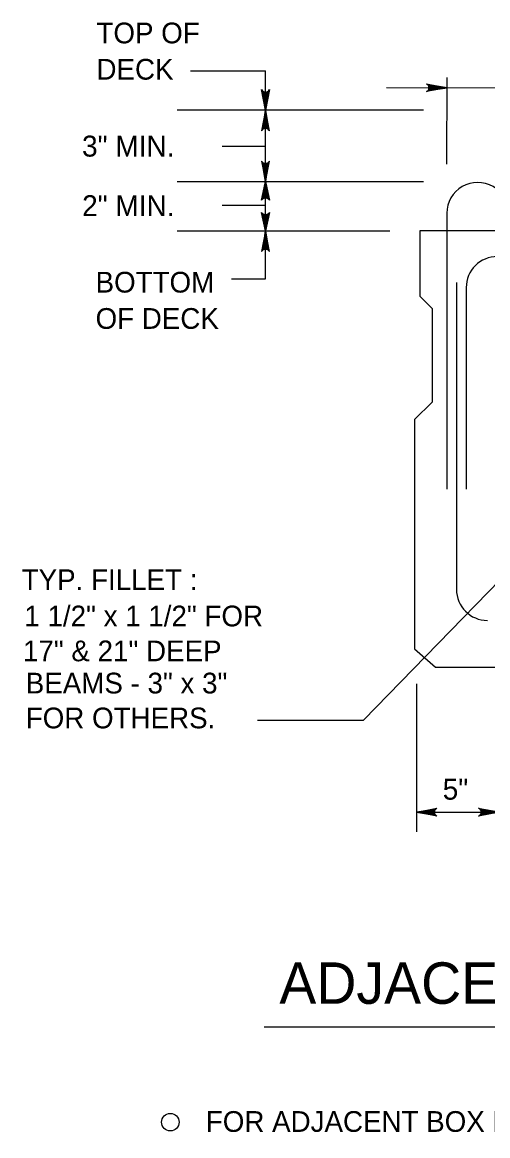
# Model space of a CAD drawing. Extents: x 639331 to 643089, y 299088 to 300975.
# Drawn here: x 640737.4 to 640804.7, y 299972.3 to 300133.4 of the extents above; entities that cross this region are included whole.
import ezdxf

# ---------------------------------------------------------------- set-up
doc = ezdxf.new("R2010")
doc.units = 0
doc.layers.add('1', color=7, linetype='Continuous')

msp = doc.modelspace()

# ---------------------------------------------------------------- linework, layer by layer
at = {"layer": '1'}
for p, q in [((640761.7, 300126.43), (640772.55, 300126.43)), ((640772.55, 300120.71), (640772.55, 300126.43)), ((640798.79, 300112.93), (640798.81, 300125.47)), ((640790.04, 300123.99), (640833.01, 300123.91)), ((640795.38, 300120.71), (640759.78, 300120.71)), ((640772.55, 300110.38), (640772.55, 300120.71)), ((640772.55, 300115.47), (640766.26, 300115.47)), ((640759.78, 300110.38), (640795.38, 300110.38)), ((640772.55, 300103.25), (640772.55, 300110.38)), ((640772.59, 300106.92), (640766.26, 300106.92)), ((640798.78, 300105.81), (640798.78, 300065.86)), ((640759.78, 300103.25), (640790.51, 300103.25)), ((640772.55, 300096.33), (640772.55, 300103.15)), ((640905.9, 300103.25), (640794.85, 300103.25)), ((640794.85, 300103.25), (640794.85, 300093.82)), ((640767.62, 300096.33), (640772.55, 300096.33)), ((640798.78, 300095.8), (640798.78, 300065.86)), ((640800.18, 300095.8), (640800.18, 300051.34)), ((640801.58, 300095.04), (640801.58, 300065.86)), ((640794.85, 300093.82), (640796.65, 300092.02)), ((640796.65, 300092.02), (640796.65, 300078.48)), ((640794.11, 300075.94), (640796.65, 300078.48)), ((640794.11, 300075.94), (640794.11, 300042.75)), ((640809.14, 300055.51), (640786.72, 300032.44)), ((640794.11, 300042.75), (640797.14, 300040.1)), ((640797.14, 300040.1), (640903.61, 300040.1)), ((640794.37, 300037.7), (640794.37, 300016.29)), ((640771.4, 300032.44), (640786.72, 300032.44)), ((640794.37, 300019.13), (640806.36, 300019.13)), ((640772.36, 299988.08), (640925.24, 299988.08))]:
    msp.add_line(p, q, dxfattribs=at)
for points in [[(640772.55, 300120.71), (640771.99, 300123.7), (640772.07, 300123.58), (640772.15, 300123.47), (640772.25, 300123.41), (640772.35, 300123.35), (640772.45, 300123.33), (640772.55, 300123.31), (640772.65, 300123.33), (640772.75, 300123.35), (640772.85, 300123.41), (640772.95, 300123.47), (640773.03, 300123.58), (640773.11, 300123.7), (640772.55, 300120.71), (640773.03, 300123.58), (640772.95, 300123.47), (640772.55, 300120.71), (640772.85, 300123.41), (640772.75, 300123.35), (640772.55, 300120.71), (640772.65, 300123.33), (640772.55, 300123.31), (640772.55, 300120.71), (640772.45, 300123.33), (640772.35, 300123.35), (640772.55, 300120.71), (640772.25, 300123.41), (640772.15, 300123.47), (640772.55, 300120.71), (640772.07, 300123.58)], [(640798.81, 300123.98), (640795.83, 300123.42), (640795.94, 300123.5), (640796.06, 300123.58), (640796.12, 300123.68), (640796.18, 300123.78), (640796.19, 300123.88), (640796.21, 300123.98), (640796.19, 300124.08), (640796.18, 300124.18), (640796.12, 300124.28), (640796.06, 300124.38), (640795.94, 300124.46), (640795.83, 300124.54), (640798.81, 300123.98), (640795.94, 300124.46), (640796.06, 300124.38), (640798.81, 300123.98), (640796.12, 300124.28), (640796.18, 300124.18), (640798.81, 300123.98), (640796.19, 300124.08), (640796.21, 300123.98), (640798.81, 300123.98), (640796.19, 300123.88), (640796.18, 300123.78), (640798.81, 300123.98), (640796.12, 300123.68), (640796.06, 300123.58), (640798.81, 300123.98), (640795.94, 300123.5)], [(640772.55, 300120.71), (640771.99, 300117.73), (640772.07, 300117.85), (640772.15, 300117.96), (640772.25, 300118.02), (640772.35, 300118.08), (640772.45, 300118.1), (640772.55, 300118.11), (640772.65, 300118.1), (640772.75, 300118.08), (640772.85, 300118.02), (640772.95, 300117.96), (640773.03, 300117.85), (640773.11, 300117.73), (640772.55, 300120.71), (640773.03, 300117.85), (640772.95, 300117.96), (640772.55, 300120.71), (640772.85, 300118.02), (640772.75, 300118.08), (640772.55, 300120.71), (640772.65, 300118.1), (640772.55, 300118.11), (640772.55, 300120.71), (640772.45, 300118.1), (640772.35, 300118.08), (640772.55, 300120.71), (640772.25, 300118.02), (640772.15, 300117.96), (640772.55, 300120.71), (640772.07, 300117.85)], [(640772.55, 300110.38), (640773.11, 300113.36), (640773.03, 300113.25), (640772.95, 300113.13), (640772.85, 300113.07), (640772.75, 300113.01), (640772.65, 300113), (640772.55, 300112.98), (640772.45, 300113), (640772.35, 300113.01), (640772.25, 300113.07), (640772.15, 300113.13), (640772.07, 300113.25), (640771.99, 300113.36), (640772.55, 300110.38), (640772.07, 300113.25), (640772.15, 300113.13), (640772.55, 300110.38), (640772.25, 300113.07), (640772.35, 300113.01), (640772.55, 300110.38), (640772.45, 300113), (640772.55, 300112.98), (640772.55, 300110.38), (640772.65, 300113), (640772.75, 300113.01), (640772.55, 300110.38), (640772.85, 300113.07), (640772.95, 300113.13), (640772.55, 300110.38), (640773.03, 300113.25)], [(640772.55, 300110.38), (640773.11, 300107.69), (640773.03, 300107.8), (640772.95, 300107.9), (640772.85, 300107.95), (640772.75, 300108.01), (640772.65, 300108.02), (640772.55, 300108.04), (640772.45, 300108.02), (640772.35, 300108.01), (640772.25, 300107.95), (640772.15, 300107.9), (640772.07, 300107.8), (640771.99, 300107.69), (640772.55, 300110.38), (640772.07, 300107.8), (640772.15, 300107.9), (640772.55, 300110.38), (640772.25, 300107.95), (640772.35, 300108.01), (640772.55, 300110.38), (640772.45, 300108.02), (640772.55, 300108.04), (640772.55, 300110.38), (640772.65, 300108.02), (640772.75, 300108.01), (640772.55, 300110.38), (640772.85, 300107.95), (640772.95, 300107.9), (640772.55, 300110.38), (640773.03, 300107.8)], [(640772.55, 300103.25), (640771.99, 300105.93), (640772.07, 300105.83), (640772.15, 300105.72), (640772.25, 300105.67), (640772.35, 300105.62), (640772.45, 300105.6), (640772.55, 300105.59), (640772.65, 300105.6), (640772.75, 300105.62), (640772.85, 300105.67), (640772.95, 300105.72), (640773.03, 300105.83), (640773.11, 300105.93), (640772.55, 300103.25), (640773.03, 300105.83), (640772.95, 300105.72), (640772.55, 300103.25), (640772.85, 300105.67), (640772.75, 300105.62), (640772.55, 300103.25), (640772.65, 300105.6), (640772.55, 300105.59), (640772.55, 300103.25), (640772.45, 300105.6), (640772.35, 300105.62), (640772.55, 300103.25), (640772.25, 300105.67), (640772.15, 300105.72), (640772.55, 300103.25), (640772.07, 300105.83)], [(640772.55, 300103.25), (640771.99, 300100.26), (640772.07, 300100.38), (640772.15, 300100.49), (640772.25, 300100.55), (640772.35, 300100.61), (640772.45, 300100.63), (640772.55, 300100.65), (640772.65, 300100.63), (640772.75, 300100.61), (640772.85, 300100.55), (640772.95, 300100.49), (640773.03, 300100.38), (640773.11, 300100.26), (640772.55, 300103.25), (640773.03, 300100.38), (640772.95, 300100.49), (640772.55, 300103.25), (640772.85, 300100.55), (640772.75, 300100.61), (640772.55, 300103.25), (640772.65, 300100.63), (640772.55, 300100.65), (640772.55, 300103.25), (640772.45, 300100.63), (640772.35, 300100.61), (640772.55, 300103.25), (640772.25, 300100.55), (640772.15, 300100.49), (640772.55, 300103.25), (640772.07, 300100.38)], [(640794.37, 300019.13), (640797.35, 300019.69), (640797.23, 300019.61), (640797.12, 300019.53), (640797.06, 300019.43), (640797, 300019.33), (640796.98, 300019.23), (640796.97, 300019.13), (640796.98, 300019.03), (640797, 300018.93), (640797.06, 300018.83), (640797.12, 300018.73), (640797.23, 300018.65), (640797.35, 300018.57), (640794.37, 300019.13), (640797.23, 300018.65), (640797.12, 300018.73), (640794.37, 300019.13), (640797.06, 300018.83), (640797, 300018.93), (640794.37, 300019.13), (640796.98, 300019.03), (640796.97, 300019.13), (640794.37, 300019.13), (640796.98, 300019.23), (640797, 300019.33), (640794.37, 300019.13), (640797.06, 300019.43), (640797.12, 300019.53), (640794.37, 300019.13), (640797.23, 300019.61)], [(640806.36, 300019.13), (640803.38, 300018.57), (640803.5, 300018.65), (640803.61, 300018.73), (640803.67, 300018.83), (640803.73, 300018.93), (640803.75, 300019.03), (640803.76, 300019.13), (640803.75, 300019.23), (640803.73, 300019.33), (640803.67, 300019.43), (640803.61, 300019.53), (640803.5, 300019.61), (640803.38, 300019.69), (640806.36, 300019.13), (640803.5, 300019.61), (640803.61, 300019.53), (640806.36, 300019.13), (640803.67, 300019.43), (640803.73, 300019.33), (640806.36, 300019.13), (640803.75, 300019.23), (640803.76, 300019.13), (640806.36, 300019.13), (640803.75, 300019.03), (640803.73, 300018.93), (640806.36, 300019.13), (640803.67, 300018.83), (640803.61, 300018.73), (640806.36, 300019.13), (640803.5, 300018.65)]]:
    msp.add_lwpolyline(points, dxfattribs=at)
msp.add_circle((640758.78, 299974.26), 1.27, dxfattribs=at)
for centre, radius, start, end in [((640803.23, 300105.81), 4.46, 359.9442, 180.0003), ((640806.08, 300095.04), 4.5, 90, 180), ((640804.66, 300051.38), 4.5, 180, 270)]:
    msp.add_arc(centre, radius, start, end, dxfattribs=at)

# ---------------------------------------------------------------- texts
for s, height, p in [('TOP OF', 3, (640748.1, 300130.4)), ('DECK', 3, (640748.1, 300125.15)), ('3" MIN.', 3.031, (640746.01, 300114.01)), ('2" MIN.', 3.031, (640746.02, 300105.39)), ('BOTTOM', 3, (640747.97, 300094.33)), ('OF DECK', 3, (640747.97, 300089.08)), ('TYP. FILLET :', 3.0008, (640737.28, 300051.27)), ('1 1/2" x 1 1/2" FOR', 3.0008, (640737.67, 300046.02)), ('17" & 21" DEEP', 3.0008, (640737.47, 300040.97)), ('BEAMS - 3" x 3"', 3.0008, (640737.87, 300036.31)), ('FOR OTHERS.', 3.0008, (640737.87, 300031.26)), ('5"', 3.031, (640798.18, 300020.94)), ('ADJACENT BOX BEAM SECTION', 6, (640774.55, 299991.39)), ('FOR ADJACENT BOX BEAMS SUPPORTING BARRIERS, SEE SHEETS 4 AND 5.', 3, (640763.92, 299972.86))]:
    msp.add_text(s, height=height, dxfattribs=at).set_placement(p)

doc.saveas('drawing.dxf')
